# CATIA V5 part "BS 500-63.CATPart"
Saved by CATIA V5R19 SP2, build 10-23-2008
Part number: BS 500-63
Bounding box of the stored display mesh (mm): x -18.951 to 18.951, y -18.952 to 18.952, z 0 to 156
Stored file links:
  C:\Users\Bora\Desktop\3D Katı model\BS serisi\BS 500\BS 500-63.CATPart
  C:\Program Files\Dassault Systemes\B19\intel_a\reffiles\standard\MetricThickPitch.txt
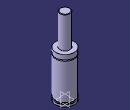
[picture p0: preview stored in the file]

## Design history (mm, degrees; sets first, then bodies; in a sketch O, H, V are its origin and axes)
Body1 (main body)
  Sketch1 on yz-plane, origin (0, 0, 0), H (0, 1, 0), V (0, 0, 1)
    point P1 (10, 155)
    point P3 (10, 155)
    point P5 (19, 82.5)
    point P6 (19, 80.5)
    point P9 (19, 82.5)
    point P14 (19, 80.5)
    line L1 (10, 155) -> (10, 92)
    arc A1 centre (9, 155) radius 1 from (10, 155) to (9, 156) ccw
    arc A2 centre (19, 81.5) radius 1 from (19, 82.5) to (19, 80.5) ccw
    line L2 (19, 0) -> (19, 4)
    line L3 (19, 82.5) -> (19, 92)
    line L4 (17, 7.5) -> (17, 4)
    line L5 (19, 7.5) -> (19, 80.5)
    line L6 (9, 156) -> (0, 156)
    point P15 (0, 156)
    line L7 (10, 92) -> (19, 92)
    line L8 (0, 0) -> (19, 0)
    line L9 (17, 7.5) -> (19, 7.5)
    line L10 (17, 4) -> (19, 4)
    coincidence: P15 V, P1 P3, P5 P9, P6 P14
    tangency: L6 A1
    horizontal: L7 H, L8 H, L9 H, L10 H
  Shaft1: profile Sketch1, axis Sketch1.V, angle 360
  Sketch2 on face of Shaft1 from Sketch1.L8, origin (0, 0, 0), H (1, 0, 0), V (0, -1, 0)
    point P1 (0, 0)
  Hole1: placed by Sketch2, at (0, 0, 0) direction (0, 0, 1), diameter 6.647, depth 4, threaded "M8", thread diameter 8, thread depth 4, pitch 1.25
